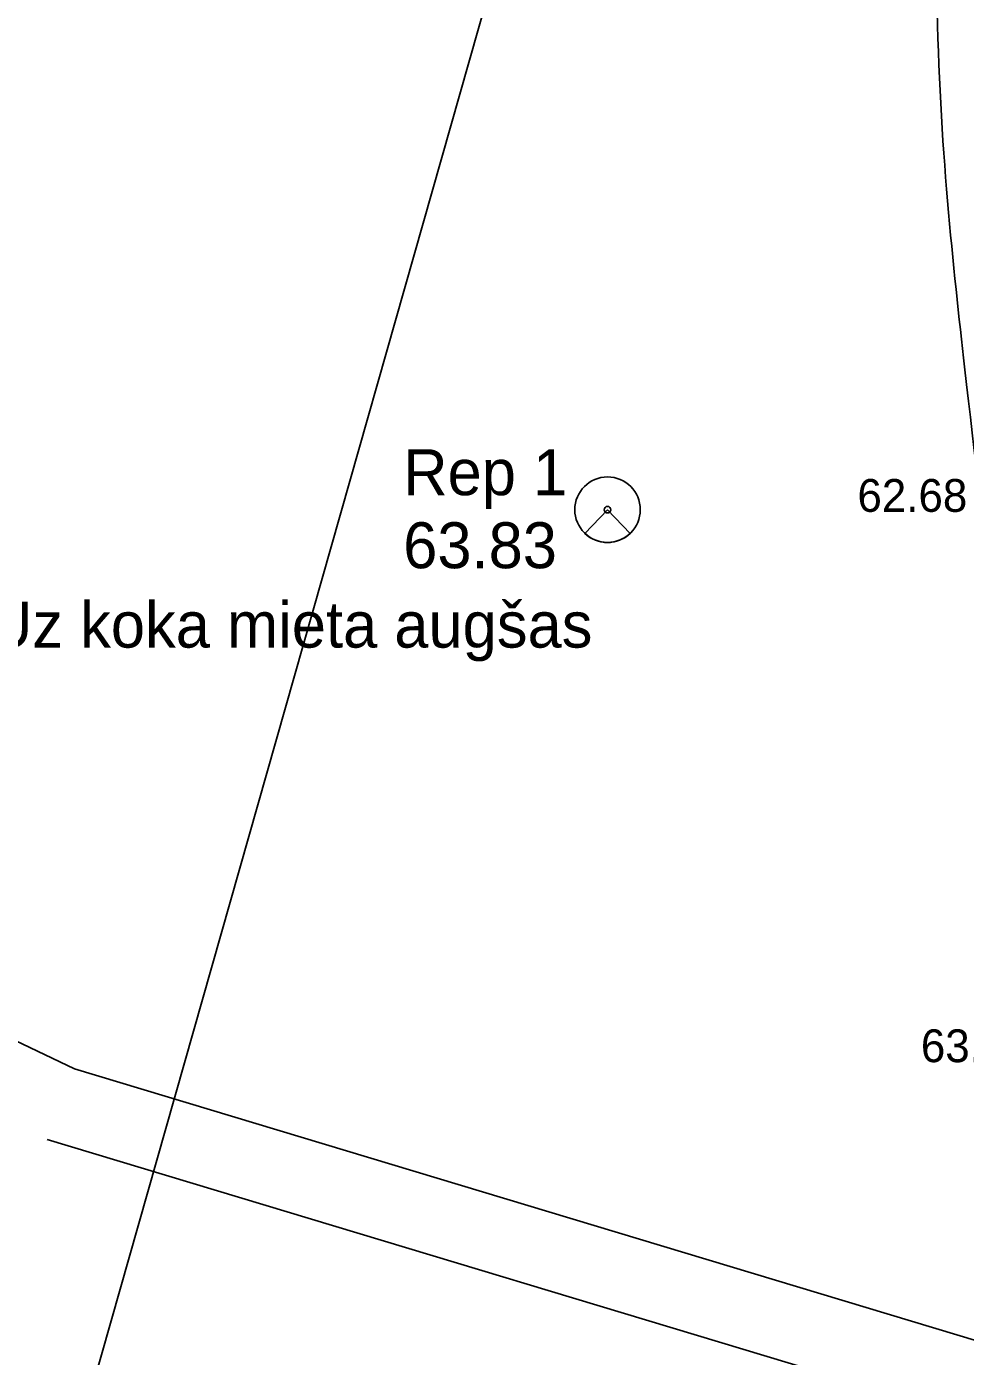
# Model space of a CAD drawing. Extents: x 616607 to 617499, y 408385 to 409695.
# Drawn here: x 617176.04 to 617190.35, y 409064.08 to 409084.35 of the extents above; entities that cross this region are included whole.
import ezdxf

# ---------------------------------------------------------------- set-up
doc = ezdxf.new("R2010")
doc.units = 0
for name, color, linetype in [('BUVE_INZE_VEKT_####_#', 7, 'Continuous'), ('GEOD_ELEM_####_####_#', 7, 'Continuous'), ('GEOD_ELEM_####_TKST_#', 7, 'Continuous'), ('RAMI_UZMR_####_####_#', 7, 'Continuous'), ('RELJ_AATZ_####_TKST_#', 7, 'Continuous'), ('RELJ_ELEM_####_####_#', 7, 'Continuous'), ('RELJ_NOGA_####_####_#', 7, 'Continuous'), ('ROBZ_IERR_####_####_#', 7, 'Continuous'), ('ROBZ_PROJ_####_####_#', 7, 'Continuous')]:
    doc.layers.add(name, color=color, linetype=linetype)

# ---------------------------------------------------------------- blocks, each defined once
blk = doc.blocks.new('PKT')
at = {"layer": 'RELJ_ELEM_####_####_#'}
blk.add_circle((0, 0), 0.05, dxfattribs=at)
blk = doc.blocks.new('PAGREP')
at = {"layer": 'GEOD_ELEM_####_####_#'}
for p, q in [((-0.348, -0.361), (0, 0)), ((0, 0), (0.343, -0.361))]:
    blk.add_line(p, q, dxfattribs=at)
blk.add_circle((0, 0), 0.499, dxfattribs=at)
blk.add_circle((0, 0), 0.499, dxfattribs=at)
blk.add_arc((-0.001, 0), 0.5, 226.1696, 313.6748, dxfattribs=at)

msp = doc.modelspace()

# ---------------------------------------------------------------- linework, layer by layer
at = {"layer": 'BUVE_INZE_VEKT_####_#'}
msp.add_lwpolyline([(617176.359, 409067.385), (617190.61, 409063.088), (617205.141, 409059.702), (617231.897, 409054.857)], dxfattribs=at)
at = {"layer": 'RAMI_UZMR_####_####_#'}
msp.add_lwpolyline([(617101.571, 408748.246), (617213.472, 409074.039), (617215.883, 409140.56), (617165.121, 409241.478), (617252.137, 409353.424), (617269.572, 409425.099), (617332.631, 409510.312), (617439.945, 409622.037), (617425.373, 409635.959), (617242.079, 409440.82), (617216.614, 409355.716), (617136.613, 409246.751), (617191.828, 409115.62), (617145.545, 408952.8)], dxfattribs=at)
at = {"layer": 'RELJ_NOGA_####_####_#'}
for points in [[(617336.806, 409523.735), (617334.087, 409521.174), (617331.368, 409518.613), (617328.65, 409516.053), (617321.193, 409509.03), (617314.57, 409501.094), (617308.568, 409492.793), (617305.546, 409488.614), (617302.537, 409484.426), (617299.516, 409480.247), (617296.49, 409476.063), (617293.469, 409471.875), (617290.436, 409467.695), (617287.772, 409464.025), (617284.965, 409460.461), (617282.252, 409456.826), (617279.55, 409453.205), (617276.887, 409449.558), (617274.256, 409445.882), (617271.624, 409442.206), (617269.17, 409438.414), (617266.782, 409434.573), (617265.581, 409432.642), (617264.455, 409430.674), (617263.346, 409428.69), (617262.228, 409426.69), (617261.169, 409424.668), (617260.166, 409422.606), (617258.56, 409419.302), (617257.132, 409415.931), (617255.903, 409412.47), (617254.682, 409409.035), (617253.531, 409405.585), (617252.579, 409402.073), (617251.627, 409398.563), (617250.683, 409395.052), (617249.746, 409391.538), (617248.81, 409388.023), (617247.876, 409384.508), (617246.956, 409380.989), (617246.456, 409379.078), (617246.028, 409377.149), (617245.649, 409375.21), (617245.269, 409373.268), (617244.984, 409371.31), (617244.622, 409369.366), (617244.259, 409367.42), (617243.878, 409365.48), (617243.456, 409363.545), (617243.245, 409362.576), (617242.967, 409361.625), (617242.691, 409360.672), (617242.413, 409359.713), (617242.093, 409358.772), (617241.734, 409357.838), (617241.092, 409356.173), (617240.315, 409354.578), (617239.389, 409353.048), (617238.465, 409351.519), (617237.498, 409350.034), (617236.402, 409348.636), (617235.3, 409347.23), (617234.195, 409345.828), (617233.083, 409344.431), (617231.973, 409343.038), (617230.863, 409341.647), (617229.743, 409340.262), (617227.764, 409337.815), (617225.693, 409335.438), (617223.461, 409333.217), (617221.215, 409330.983), (617218.873, 409328.856), (617216.607, 409326.646), (617214.346, 409324.442), (617212.093, 409322.231), (617209.875, 409319.98), (617208.771, 409318.86), (617207.791, 409317.635), (617206.772, 409316.432), (617205.753, 409315.229), (617204.825, 409314.017), (617203.96, 409312.646), (617203.768, 409312.342), (617203.633, 409312.004), (617203.62, 409311.655), (617203.607, 409311.284), (617203.603, 409310.913), (617203.599, 409310.542), (617203.595, 409310.167), (617203.603, 409309.793), (617203.596, 409309.419), (617203.588, 409309.066), (617203.48, 409308.714), (617203.309, 409308.4), (617202.615, 409307.13), (617201.9, 409305.914), (617201.16, 409304.689), (617200.419, 409303.462), (617199.689, 409302.232), (617198.921, 409301.021), (617197.385, 409298.6), (617195.744, 409296.251), (617194.012, 409293.966), (617188.331, 409286.47), (617182.548, 409279.072), (617176.617, 409271.78), (617175.091, 409269.904), (617173.565, 409268.03), (617172.006, 409266.181), (617170.46, 409264.348), (617168.875, 409262.548), (617167.326, 409260.717), (617165.749, 409258.854), (617164.19, 409256.978), (617162.652, 409255.082), (617161.86, 409254.106), (617161.109, 409253.1), (617160.341, 409252.105), (617159.552, 409251.081), (617158.796, 409250.055), (617158.061, 409248.97), (617157.091, 409247.54), (617156.549, 409245.874), (617156.301, 409244.175), (617156.178, 409243.327), (617156.153, 409242.478), (617156.175, 409241.631), (617156.198, 409240.798), (617156.24, 409239.966), (617156.347, 409239.134), (617156.709, 409236.311), (617157.141, 409233.481), (617158.294, 409230.866), (617161.329, 409223.986), (617164.552, 409217.339), (617167.894, 409210.677), (617170.758, 409204.966), (617173.578, 409199.236), (617176.506, 409193.56), (617179.423, 409187.907), (617182.384, 409182.277), (617185.301, 409176.624), (617188.243, 409170.922), (617191.171, 409165.213), (617194.071, 409159.489), (617195.541, 409156.585), (617196.952, 409153.652), (617198.382, 409150.727), (617199.832, 409147.761), (617201.227, 409144.774), (617202.61, 409141.772), (617203.681, 409139.449), (617204.533, 409137.047), (617205.282, 409134.589), (617206.022, 409132.164), (617206.554, 409129.71), (617206.943, 409127.212), (617207.329, 409124.726), (617207.611, 409122.242), (617207.809, 409119.738), (617208.005, 409117.248), (617208.126, 409114.753), (617208.097, 409112.263), (617208.074, 409110.266), (617207.983, 409108.256), (617207.635, 409106.282), (617207.283, 409104.281), (617206.913, 409102.294), (617206.558, 409100.3), (617206.203, 409098.306), (617205.85, 409096.331), (617205.506, 409094.315), (617205.165, 409092.324), (617205.06, 409090.322), (617205.116, 409088.325), (617205.171, 409086.355), (617205.316, 409084.384), (617205.484, 409082.414), (617205.653, 409080.435), (617205.914, 409078.469), (617206.09, 409076.495), (617206.126, 409076.085), (617206.005, 409075.66), (617206.103, 409075.26)], [(617191.5, 409068.875), (617191.187, 409071.639), (617190.873, 409074.403), (617190.56, 409077.167), (617188.889, 409091.892), (617197.619, 409106.66), (617195.165, 409121.386), (617194.844, 409123.312), (617194.157, 409125.135), (617193.325, 409126.9), (617187.756, 409138.717), (617181.857, 409150.154), (617176.29, 409161.887), (617165.241, 409185.172), (617154.985, 409208.835), (617144.902, 409232.447), (617143.246, 409236.327), (617146.946, 409242.229), (617143.832, 409245.09), (617142.81, 409246.028), (617141.789, 409246.966), (617140.768, 409247.904)]]:
    msp.add_open_spline(points, degree=3, dxfattribs=at)
at = {"layer": 'ROBZ_IERR_####_####_#'}
msp.add_lwpolyline([(617233.239, 409055.706), (617229.417, 409056.382), (617205.386, 409060.826), (617190.906, 409064.2), (617176.774, 409068.461)], dxfattribs=at)
at = {"layer": 'ROBZ_PROJ_####_####_#'}
msp.add_lwpolyline([(617175.523, 409069.057), (617176.774, 409068.461), (617190.906, 409064.2), (617205.386, 409060.826), (617229.417, 409056.382), (617232.944, 409055.758)], dxfattribs=at)

# ---------------------------------------------------------------- block references
at = {"layer": 'GEOD_ELEM_####_####_#'}
msp.add_blockref('PAGREP', (617184.894, 409076.983), dxfattribs=at)
at = {"layer": 'RELJ_ELEM_####_####_#'}
msp.add_blockref('PKT', (617184.894, 409076.983), dxfattribs=at)

# ---------------------------------------------------------------- texts
at = {"layer": 'GEOD_ELEM_####_TKST_#'}
for s, p in [('Rep 1', (617181.781, 409077.204)), ('63.83', (617181.781, 409076.091)), ('Uz koka mieta augšas', (617175.455, 409074.881))]:
    msp.add_text(s, height=0.7, dxfattribs=at).set_placement(p)
at = {"layer": 'RELJ_AATZ_####_TKST_#'}
for s, p in [('62.68', (617188.701, 409076.95)), ('63.67', (617189.667, 409068.563))]:
    msp.add_text(s, height=0.5, dxfattribs=at).set_placement(p)

doc.saveas('drawing.dxf')
